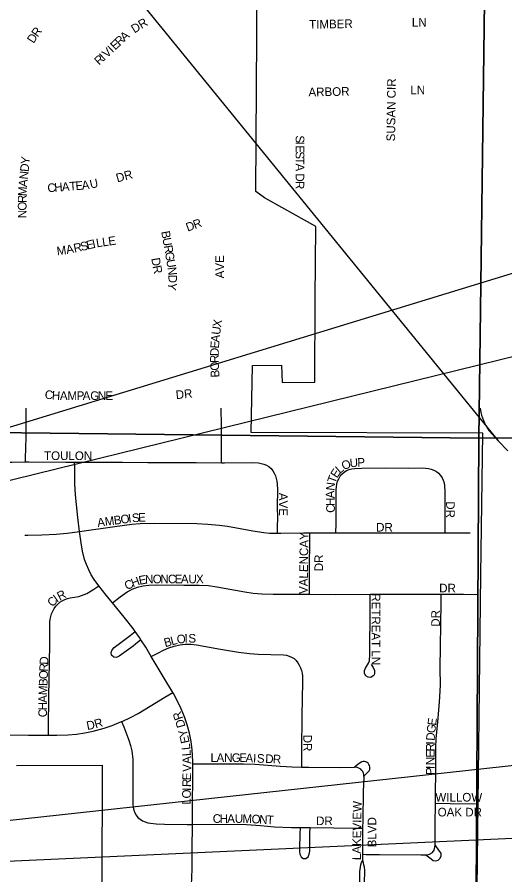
# Model space of a CAD drawing. Extents: x -9.1 to 34, y -3.1 to 22.
# Drawn here: x 6.722 to 7.257, y 18.275 to 19.215 of the extents above; entities that cross this region are included whole.
import ezdxf

# ---------------------------------------------------------------- set-up
doc = ezdxf.new("R2010")
doc.units = 0
for name, color, linetype in [('GM_X_City_Street', 7, 'Continuous'), ('GM_X_City_Street_Text', 7, 'Continuous'), ('GM_X_Corporation', 7, 'Continuous'), ('GM_X_Section', 7, 'Continuous'), ('GM_X_State_Route', 7, 'Continuous'), ('GM_X_Township_Subdivision_Text', 7, 'Continuous'), ('SH_Text', 7, 'Continuous')]:
    doc.layers.add(name, color=color, linetype=linetype)

msp = doc.modelspace()

# ---------------------------------------------------------------- linework, layer by layer
at = {"layer": 'GM_X_City_Street'}
for points in [[(6.73131, 18.72726), (6.73139, 18.73106), (6.73186, 18.75455), (6.73198, 18.77632), (6.73198, 18.78608)], [(6.94613, 18.72645), (6.94618, 18.7316), (6.94637, 18.75309), (6.94612, 18.76739), (6.9458, 18.78608)], [(6.66295, 18.72745), (6.68545, 18.72726), (6.69472, 18.72716), (6.71645, 18.72713), (6.73131, 18.72726)], [(6.73131, 18.72726), (6.73511, 18.7273), (6.77549, 18.7272), (6.78522, 18.72717)], [(6.79055, 18.65112), (6.78853, 18.66638), (6.78608, 18.6911), (6.78535, 18.70347), (6.78523, 18.72292), (6.78522, 18.72717)], [(6.78522, 18.72717), (6.83763, 18.72698), (6.86558, 18.72672), (6.91839, 18.72666), (6.94613, 18.72645)], [(6.94613, 18.72645), (6.94946, 18.72643), (6.98052, 18.72662), (6.98673, 18.72623), (6.9898, 18.72574), (6.9928, 18.72495), (6.99567, 18.72377), (6.99833, 18.72216), (7.00063, 18.72009), (7.0025, 18.71761), (7.00406, 18.71492), (7.00531, 18.71208), (7.00624, 18.70912), (7.00692, 18.70609), (7.00733, 18.70301), (7.0075, 18.69681), (7.00736, 18.67816), (7.00751, 18.66574), (7.0073, 18.65642), (7.00714, 18.64926)], [(7.07173, 18.6496), (7.07195, 18.6595), (7.07215, 18.66884), (7.07207, 18.69689), (7.07225, 18.7), (7.07272, 18.70307), (7.07357, 18.70607), (7.07479, 18.70893), (7.07637, 18.71161), (7.07834, 18.71402), (7.08063, 18.71614), (7.08325, 18.71781), (7.08613, 18.71899), (7.08914, 18.71979), (7.09223, 18.7202), (7.10031, 18.72042), (7.12648, 18.7207), (7.15141, 18.72065), (7.167, 18.72075), (7.1701, 18.72057), (7.17319, 18.72015), (7.17622, 18.7194), (7.17914, 18.71833), (7.18189, 18.71687), (7.18433, 18.71495), (7.18642, 18.71263), (7.18811, 18.71002), (7.18943, 18.7072), (7.19038, 18.70424), (7.1909, 18.70117), (7.19111, 18.69494), (7.19102, 18.67001), (7.19105, 18.65755), (7.19107, 18.64966)], [(6.79055, 18.65112), (6.8293, 18.65669), (6.84775, 18.65909), (6.85702, 18.65977), (6.87252, 18.66006), (6.91905, 18.6598), (6.93144, 18.6593), (6.94378, 18.65815), (6.95299, 18.65685), (6.98048, 18.6519), (6.99271, 18.64994), (6.99889, 18.64943), (7.00714, 18.64926)], [(6.73068, 18.64718), (6.73378, 18.64715), (6.74929, 18.64734), (6.76478, 18.648), (6.77712, 18.64916), (6.79055, 18.65112)], [(6.81163, 18.5914), (6.80658, 18.59837), (6.80342, 18.60366), (6.80059, 18.60913), (6.79815, 18.61477), (6.79613, 18.62058), (6.79385, 18.62953), (6.79219, 18.63866), (6.79055, 18.65112)], [(7.00714, 18.64926), (7.01128, 18.64914), (7.03609, 18.64956), (7.04323, 18.64957)], [(7.04282, 18.58242), (7.04277, 18.58803), (7.04261, 18.61362), (7.04305, 18.63921), (7.04323, 18.64957)], [(7.04323, 18.64957), (7.07173, 18.6496)], [(7.07173, 18.6496), (7.11983, 18.64966), (7.19107, 18.64966)], [(7.19107, 18.64966), (7.19426, 18.64966), (7.21907, 18.64958)], [(6.75662, 18.42788), (6.75669, 18.43591), (6.75701, 18.47037), (6.75799, 18.52677), (6.75797, 18.5487), (6.75811, 18.55183), (6.75844, 18.55495), (6.75906, 18.55802), (6.75997, 18.56102), (6.76119, 18.56389), (6.76274, 18.56662), (6.76459, 18.56914), (6.76672, 18.57145), (6.76908, 18.5735), (6.77168, 18.57525), (6.77447, 18.57668), (6.7774, 18.57778), (6.78043, 18.57855), (6.78971, 18.58006), (6.79272, 18.58092), (6.79853, 18.58323), (6.80315, 18.58592), (6.80614, 18.58791), (6.81163, 18.5914)], [(6.8266, 18.57294), (6.8197, 18.58118), (6.81163, 18.5914)], [(6.8266, 18.57294), (6.83529, 18.57952), (6.84025, 18.58328), (6.84288, 18.58496), (6.84559, 18.58649), (6.84841, 18.58782), (6.85426, 18.58997), (6.86031, 18.59147), (6.86648, 18.59235), (6.87494, 18.59256), (6.90494, 18.59235), (6.92162, 18.59215), (6.93191, 18.59182), (6.94117, 18.59054), (6.97184, 18.58491), (6.98109, 18.58359), (6.9904, 18.58273), (7.00286, 18.58238), (7.04027, 18.58245), (7.04282, 18.58242)], [(7.04282, 18.58242), (7.07144, 18.58208), (7.10935, 18.58229)], [(7.11044, 18.50539), (7.11255, 18.50223), (7.11401, 18.49866), (7.11403, 18.49547), (7.11361, 18.4942), (7.11264, 18.49283), (7.11006, 18.49127), (7.10702, 18.49136), (7.10446, 18.493), (7.10299, 18.49566), (7.103, 18.49868), (7.1042, 18.50147), (7.10753, 18.50667), (7.10851, 18.50952), (7.10896, 18.51638), (7.10902, 18.52488), (7.10935, 18.55869), (7.10935, 18.57404), (7.10935, 18.58229)], [(7.10935, 18.58229), (7.14938, 18.5825), (7.17744, 18.58229), (7.1872, 18.58231)], [(7.18088, 18.35349), (7.18098, 18.37121), (7.18122, 18.38029), (7.18134, 18.39275), (7.18138, 18.41455), (7.18176, 18.42387), (7.18337, 18.44248), (7.18535, 18.46419), (7.18627, 18.48284), (7.18624, 18.50152), (7.18709, 18.57312), (7.1872, 18.58231)], [(7.1872, 18.58231), (7.21173, 18.58234), (7.22731, 18.58217)], [(6.85171, 18.54148), (6.84922, 18.54499), (6.83968, 18.55731), (6.8266, 18.57294)], [(6.85791, 18.53247), (6.8518, 18.52762), (6.84932, 18.52565), (6.83923, 18.51802), (6.83401, 18.51436), (6.83109, 18.51323), (6.82802, 18.5135), (6.82577, 18.51558), (6.82521, 18.51866), (6.82626, 18.52159), (6.82841, 18.52388), (6.84609, 18.53724), (6.85171, 18.54148)], [(6.85791, 18.53247), (6.85643, 18.53481), (6.85171, 18.54148)], [(6.86924, 18.51399), (6.86312, 18.52428), (6.85791, 18.53247)], [(6.86924, 18.51399), (6.87725, 18.51819), (6.88275, 18.52106), (6.88844, 18.52355), (6.89435, 18.52546), (6.90041, 18.52681), (6.90656, 18.52754), (6.91277, 18.52759), (6.91895, 18.52701), (6.94529, 18.52225), (6.96483, 18.51906), (6.97714, 18.5175), (6.98641, 18.51672), (7.01434, 18.51609), (7.0174, 18.51562), (7.02035, 18.51468), (7.02321, 18.51346), (7.02584, 18.51182), (7.0281, 18.5097), (7.03, 18.50725), (7.0316, 18.50459), (7.03289, 18.50177), (7.03388, 18.49883), (7.03455, 18.4958), (7.03492, 18.49272), (7.03501, 18.48652), (7.0344, 18.44927), (7.03408, 18.41202), (7.03401, 18.3964), (7.034, 18.39302)], [(6.8928, 18.47486), (6.88219, 18.49219), (6.86924, 18.51399)], [(6.83673, 18.4429), (6.83803, 18.44346), (6.84648, 18.44742), (6.85473, 18.45179), (6.8681, 18.45973), (6.88401, 18.46948), (6.8928, 18.47486)], [(6.91492, 18.39653), (6.91492, 18.39929), (6.9141, 18.41176), (6.91296, 18.42107), (6.91119, 18.43031), (6.90869, 18.43936), (6.90564, 18.44823), (6.90211, 18.45692), (6.89809, 18.46539), (6.89357, 18.47361), (6.8928, 18.47486)], [(6.75662, 18.42788), (6.76559, 18.42791), (6.77802, 18.42831), (6.78731, 18.42916), (6.79652, 18.43059), (6.80566, 18.43252), (6.81769, 18.43572), (6.82651, 18.43873), (6.83673, 18.4429)], [(6.83673, 18.4429), (6.83906, 18.43698), (6.8447, 18.42259), (6.84649, 18.41671), (6.84779, 18.41068), (6.84889, 18.40147), (6.84901, 18.39467), (6.84892, 18.38605), (6.84884, 18.3551), (6.84899, 18.352), (6.84943, 18.34894), (6.8502, 18.34595), (6.85131, 18.34305), (6.85273, 18.34031), (6.85459, 18.33783), (6.85692, 18.33581), (6.85954, 18.33416), (6.86236, 18.33291), (6.86533, 18.33203), (6.86836, 18.33142), (6.87451, 18.33076), (6.8838, 18.3306), (6.90856, 18.33013), (6.91449, 18.33017)], [(6.47618, 18.42982), (6.49796, 18.42942), (6.53842, 18.42903), (6.59132, 18.4287), (6.65668, 18.42834), (6.68787, 18.42821), (6.73446, 18.42779), (6.75662, 18.42788)], [(7.10244, 18.38302), (7.10707, 18.38794), (7.10804, 18.38897), (7.10879, 18.39025), (7.10907, 18.39173), (7.10896, 18.39319), (7.10858, 18.39483), (7.10793, 18.39595), (7.10705, 18.3972), (7.10594, 18.39809), (7.10464, 18.39868), (7.10318, 18.39904), (7.10169, 18.39917), (7.10024, 18.39885), (7.09725, 18.39705), (7.09197, 18.39274)], [(6.91449, 18.33017), (6.91458, 18.33394), (6.91443, 18.35262), (6.91493, 18.38058), (6.91492, 18.39653)], [(6.91492, 18.39653), (6.92343, 18.39655), (6.97029, 18.39667), (6.98277, 18.39624), (7.01079, 18.39395), (7.02326, 18.39327), (7.034, 18.39302)], [(7.034, 18.39302), (7.042, 18.39283), (7.07635, 18.39251), (7.09197, 18.39274)], [(7.10244, 18.38302), (7.10226, 18.38505), (7.10193, 18.38646), (7.10123, 18.388), (7.10011, 18.38941), (7.09898, 18.39069), (7.09701, 18.39182), (7.09509, 18.39242), (7.09197, 18.39274)], [(7.10142, 18.32606), (7.10148, 18.33468), (7.10197, 18.36621), (7.10254, 18.38195), (7.10244, 18.38302)], [(7.18056, 18.30785), (7.18061, 18.30847), (7.18053, 18.33015), (7.18088, 18.35349)], [(7.18088, 18.35349), (7.19697, 18.35321), (7.22468, 18.35274)], [(6.91332, 18.25935), (6.91344, 18.26369), (6.91391, 18.28107), (6.91402, 18.30286), (6.91449, 18.33017)], [(6.91449, 18.33017), (6.9519, 18.33035), (6.97356, 18.32995), (6.989, 18.32894), (7.00442, 18.32764), (7.02298, 18.32691), (7.03255, 18.3268)], [(7.03255, 18.3268), (7.03225, 18.31966), (7.03167, 18.30388), (7.03168, 18.30069), (7.03211, 18.29753), (7.03347, 18.29467), (7.03588, 18.2929), (7.03889, 18.29296), (7.04125, 18.29477), (7.04254, 18.2976), (7.043, 18.30076), (7.04331, 18.31975), (7.04343, 18.32669)], [(7.03255, 18.3268), (7.04343, 18.32669)], [(7.04343, 18.32669), (7.06941, 18.32641), (7.09107, 18.32607), (7.09417, 18.32607), (7.10142, 18.32606)], [(7.10124, 18.29743), (7.10142, 18.32606)], [(7.17032, 18.29698), (7.17132, 18.297), (7.17453, 18.29758), (7.1776, 18.29927), (7.17951, 18.30212), (7.18036, 18.30529), (7.18056, 18.30785)], [(7.17032, 18.29698), (7.17608, 18.29242), (7.17834, 18.29062), (7.18121, 18.29019), (7.18396, 18.29112), (7.18603, 18.29316), (7.18717, 18.29582), (7.18704, 18.29873), (7.18538, 18.30105), (7.18056, 18.30785)], [(7.1011, 18.29068), (7.10124, 18.29688), (7.10124, 18.29743)], [(7.10124, 18.29743), (7.105, 18.29737), (7.11936, 18.29716), (7.16505, 18.29689), (7.17032, 18.29698)], [(7.09793, 18.25958), (7.09804, 18.2663), (7.09803, 18.27878), (7.09859, 18.28342), (7.09908, 18.28576), (7.09995, 18.2883), (7.1011, 18.29068)], [(7.10323, 18.25957), (7.10325, 18.26594), (7.10331, 18.27963), (7.10293, 18.28346), (7.10249, 18.28593), (7.10198, 18.2882), (7.1011, 18.29068)]]:
    msp.add_lwpolyline(points, dxfattribs=at)
at = {"layer": 'GM_X_Corporation'}
msp.add_lwpolyline([(6.72153, 18.39482), (6.81526, 18.39497), (6.81489, 18.25955), (7.06726, 18.25968), (7.22647, 18.25948), (7.23082, 18.6038), (7.23301, 18.75869), (6.97885, 18.75965), (6.98041, 18.83311), (7.01204, 18.83341), (7.01282, 18.81434), (7.0487, 18.81465), (7.04916, 18.90613), (7.04957, 18.98521), (7.01581, 19.00411), (6.9933, 19.01665), (6.98403, 19.02347), (6.98564, 19.30764)], dxfattribs=at)
at = {"layer": 'GM_X_Section'}
for points in [[(8.25963, 19.78018), (8.25959, 19.77298), (8.24647, 18.75468), (7.22846, 18.75339), (7.24082, 19.71069)], [(6.2379, 19.76083), (7.24082, 19.71069), (7.22846, 18.75339), (6.22532, 18.76489)], [(6.22532, 18.76489), (7.22846, 18.75339), (7.22268, 17.75665), (6.22405, 17.76169)], [(7.22846, 18.75339), (8.24647, 18.75468), (8.23342, 17.74851), (7.22268, 17.75665)]]:
    msp.add_lwpolyline(points, close=True, dxfattribs=at)
at = {"layer": 'GM_X_State_Route'}
msp.add_line((6.83569, 19.25808), (7.24952, 18.7505), dxfattribs=at)
msp.add_lwpolyline([(7.23009, 18.78608), (7.23082, 18.78147), (7.23152, 18.7785), (7.2324, 18.77559), (7.23346, 18.77274), (7.23471, 18.76998), (7.23615, 18.76729), (7.23954, 18.76188), (7.24334, 18.75741), (7.24952, 18.7505), (7.26039, 18.73947)], dxfattribs=at)
at = {"layer": 'SH_Text'}
for points in [[(9.67988, 19.67264), (5.74668, 18.46968), (9.67988, 19.43664)], [(9.7171, 18.42605), (6.00368, 18.25734), (9.7171, 18.66205)]]:
    msp.add_lwpolyline(points, close=True, dxfattribs=at)

# ---------------------------------------------------------------- texts
at = {"layer": 'GM_X_City_Street_Text'}
for s, rotation, p in [('DR', 32.01403, (6.8508, 19.19664)), ('R', 54.47079, (6.74467, 19.1921)), ('A', 41.53551, (6.83992, 19.18765)), ('D', 56.84329, (6.74017, 19.1852)), ('E', 43.37648, (6.82968, 19.17798)), ('R', 43.39198, (6.83453, 19.18255)), ('V', 43.36165, (6.82059, 19.16939)), ('I', 43.36165, (6.82665, 19.17511)), ('R', 43.36832, (6.81211, 19.16138)), ('I', 43.36165, (6.81756, 19.16653)), ('Y', 84.39596, (6.73545, 19.05304)), ('D', 84.39596, (6.73464, 19.04475)), ('N', 84.39596, (6.73382, 19.03646)), ('U', 12.59236, (6.80287, 19.02667)), ('DR', 15.52599, (6.83203, 19.03347)), ('M', 86.48274, (6.73241, 19.01827)), ('A', 84.46122, (6.73302, 19.02816)), ('C', 4.30187, (6.75571, 19.0227)), ('H', 4.28806, (6.76319, 19.02327)), ('A', 4.28806, (6.7715, 19.02389)), ('T', 4.306, (6.77981, 19.02451)), ('E', 4.29392, (6.78646, 19.02502)), ('A', 6.40317, (6.79349, 19.02555)), ('R', 89.92712, (6.73241, 19.01092)), ('O', 89.94783, (6.7324, 19.00259)), ('N', 89.93441, (6.73239, 18.99426)), ('D', 20.05968, (6.9092, 18.97952)), ('R', 20.23715, (6.91705, 18.98239)), ('L', 9.33204, (6.80951, 18.96231)), ('L', 7.75532, (6.81602, 18.96338)), ('E', 8.16328, (6.82269, 18.96429)), ('B', 280.03331, (6.8801, 18.97958)), ('U', 280.03886, (6.8814, 18.9722)), ('M', 7.80043, (6.76618, 18.95356)), ('A', 10.92661, (6.77665, 18.95501)), ('R', 11.941, (6.78501, 18.95663)), ('S', 13.74383, (6.79266, 18.95825)), ('E', 13.89609, (6.79916, 18.95984)), ('I', 12.60468, (6.80558, 18.96143)), ('R', 280.0359, (6.88286, 18.96399)), ('G', 280.03886, (6.88416, 18.95661)), ('AVE', 90, (6.94906, 18.92842)), ('D', 279.53061, (6.8692, 18.95023)), ('U', 280.03886, (6.88562, 18.9484)), ('R', 281.35718, (6.87064, 18.94169)), ('N', 276.46088, (6.88705, 18.94035)), ('D', 271.74896, (6.88797, 18.93228)), ('Y', 261.35684, (6.88825, 18.9244)), ('X', 81.15578, (6.94577, 18.87435)), ('U', 82.37068, (6.94467, 18.86614)), ('E', 86.28223, (6.94341, 18.85137)), ('A', 84.13283, (6.94383, 18.85793)), ('D', 88.7323, (6.94323, 18.84314)), ('R', 90.70433, (6.94332, 18.83573)), ('O', 92.68776, (6.94371, 18.82749)), ('B', 92.67203, (6.94406, 18.82)), ('C', 352.5979, (6.75192, 18.79685)), ('H', 355.96149, (6.75996, 18.79583)), ('A', 359.92533, (6.76899, 18.79522)), ('M', 0.00012, (6.77733, 18.79521)), ('P', 0.00001, (6.78734, 18.79521)), ('A', 0.00001, (6.794, 18.79521)), ('G', 0.00001, (6.80233, 18.79521)), ('N', 0.00001, (6.81067, 18.79521)), ('E', 0.00001, (6.819, 18.79521)), ('DR', 6.00236, (6.89655, 18.79603)), ('TOULON', 0.00001, (6.75167, 18.72938)), ('O', 26.34021, (7.08064, 18.71795)), ('U', 4.17907, (7.08718, 18.72139)), ('P', 2.13121, (7.0954, 18.722)), ('E', 56.77222, (7.0729, 18.70892)), ('L', 40.49462, (7.07609, 18.71396)), ('T', 69.50791, (7.07082, 18.70317)), ('N', 83.38464, (7.07, 18.69548)), ('AVE', 270, (7.00929, 18.69343)), ('A', 91.68341, (7.07026, 18.68751)), ('H', 91.68341, (7.07051, 18.67918)), ('DR', 270, (7.19262, 18.68426)), ('S', 5.03365, (6.84847, 18.66109)), ('E', 1.6397, (6.85496, 18.66167)), ('C', 91.67612, (7.07073, 18.67169)), ('A', 7.71595, (6.8106, 18.65602)), ('M', 7.7102, (6.81886, 18.65714)), ('B', 7.70167, (6.82876, 18.65848)), ('O', 7.6943, (6.83619, 18.65949)), ('I', 6.88097, (6.84442, 18.6606)), ('DR', 0.00001, (7.11584, 18.65104)), ('VALENCAY', 89.24288, (7.04072, 18.58262)), ('DR', 90, (7.05767, 18.60759)), ('C', 25.56568, (6.8425, 18.58667)), ('H', 20.38463, (6.84906, 18.58982)), ('E', 11.35815, (6.85649, 18.59261)), ('N', 3.14952, (6.86267, 18.59388)), ('O', 0.28418, (6.87087, 18.59433)), ('N', 0.00001, (6.87919, 18.59438)), ('C', 0.00001, (6.88752, 18.59438)), ('E', 0.00001, (6.89502, 18.59438)), ('A', 0.00001, (6.90168, 18.59438)), ('U', 0.00001, (6.91002, 18.59438)), ('X', 0.00001, (6.91835, 18.59438)), ('R', 26.83659, (6.76881, 18.57522)), ('DR', 0.00001, (7.18501, 18.58437)), ('C', 47.3359, (6.76106, 18.56781)), ('I', 35.7766, (6.76576, 18.57299)), ('RETREAT LN', 270, (7.11092, 18.58343)), ('DR', 90, (7.18573, 18.54676)), ('B', 15.18483, (6.88453, 18.52431)), ('L', 15.19247, (6.89177, 18.52627)), ('O', 8.57832, (6.89792, 18.52796)), ('I', 2.01109, (6.90588, 18.52918)), ('S', 0.43715, (6.90997, 18.52932)), ('D', 87.88738, (6.75619, 18.50498)), ('R', 87.86272, (6.75591, 18.49748)), ('O', 87.8797, (6.7556, 18.48915)), ('B', 87.88699, (6.75532, 18.48166)), ('M', 88.05079, (6.75498, 18.47167)), ('A', 89.43164, (6.7549, 18.4634)), ('C', 89.9757, (6.75489, 18.44759)), ('H', 89.98125, (6.7549, 18.45509)), ('R', 16.36962, (6.80829, 18.43531)), ('R', 110.41275, (6.90438, 18.44638)), ('E', 83.12575, (7.18153, 18.43804)), ('D', 10.52969, (6.7991, 18.43355)), ('D', 105.69024, (6.90689, 18.43755)), ('G', 83.25185, (7.18055, 18.42977)), ('Y', 105.49352, (6.90981, 18.42707)), ('E', 102.35255, (6.91137, 18.42001)), ('DR', 270, (7.03595, 18.42843)), ('D', 85.69013, (7.17994, 18.42157)), ('L', 95.6078, (6.91221, 18.41217)), ('R', 89.95142, (7.17991, 18.41009)), ('I', 89.60666, (7.17992, 18.41757)), ('L', 94.46877, (6.91275, 18.40532)), ('L', 359.97268, (6.93417, 18.39854)), ('A', 359.99285, (6.94084, 18.39854)), ('N', 359.97814, (6.94918, 18.39854)), ('G', 359.97814, (6.95751, 18.39853)), ('E', 359.04379, (6.9658, 18.39853)), ('E', 89.95718, (7.17991, 18.40342)), ('A', 92.46155, (6.91313, 18.39663)), ('A', 357.8142, (6.97241, 18.39842)), ('I', 357.68319, (6.98073, 18.3981)), ('S', 357.64932, (6.9849, 18.39793)), ('D', 357.66047, (6.99406, 18.39756)), ('R', 357.66516, (7.00238, 18.39722)), ('N', 89.95627, (7.1799, 18.39509)), ('V', 89.11445, (6.91301, 18.3877)), ('P', 89.94534, (7.17989, 18.38425)), ('I', 89.95725, (7.1799, 18.39092)), ('E', 89.01647, (6.91285, 18.37851)), ('R', 89.02856, (6.91272, 18.37101)), ('O', 89.0355, (6.91251, 18.3585)), ('I', 89.05803, (6.91265, 18.36684)), ('WILLOW', 0.00001, (7.18084, 18.35521)), ('L', 89.01647, (6.91239, 18.35184)), ('LAKEVIEW', 89.2143, (7.09906, 18.29099)), ('OAK DR', 0.00001, (7.18334, 18.33891)), ('C', 359.97571, (6.93667, 18.33188)), ('H', 359.97035, (6.94417, 18.33187)), ('A', 359.97035, (6.9525, 18.33187)), ('U', 359.97035, (6.96084, 18.33187)), ('M', 358.25105, (6.96909, 18.33187)), ('O', 356.96079, (6.97903, 18.33156)), ('N', 356.91715, (6.98735, 18.33112)), ('T', 356.9111, (6.99567, 18.33067)), ('DR', 0.00001, (7.05001, 18.32937)), ('BLVD', 90, (7.11601, 18.30509))]:
    msp.add_text(s, height=0.00947, rotation=rotation, dxfattribs=at).set_placement(p)
at = {"layer": 'GM_X_Township_Subdivision_Text'}
for s, rotation, p in [('TIMBER', 1.10106, (7.04247, 19.20183)), ('LN', 0.00001, (7.15501, 19.20434)), ('SUSAN CIR', 89.20364, (7.13656, 19.07847)), ('ARBOR', 1.20033, (7.04173, 19.1277)), ('LN', 0.00001, (7.15334, 19.1302)), ('S', 269.91802, (7.02762, 19.08509)), ('I', 269.93912, (7.02761, 19.07842)), ('S', 269.93222, (7.0276, 19.06759)), ('E', 269.91802, (7.02761, 19.07426)), ('T', 269.91802, (7.0276, 19.06092)), ('A', 269.92532, (7.02759, 19.05425)), ('D', 269.92532, (7.02757, 19.04342)), ('R', 269.34424, (7.02756, 19.03511))]:
    msp.add_text(s, height=0.00947, rotation=rotation, dxfattribs=at).set_placement(p)

doc.saveas('drawing.dxf')
